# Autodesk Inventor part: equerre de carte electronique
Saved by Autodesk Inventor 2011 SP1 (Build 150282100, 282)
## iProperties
Created: 2010-12
Part Number: equerre de carte electronique
Document SubType Name: Modeling
Designer: eric
Density: 1 g/cm^3
Author: eric
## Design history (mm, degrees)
feature "Base1"
node "Solide1"
node "Corps solides"
node "Corps surfaciques"
